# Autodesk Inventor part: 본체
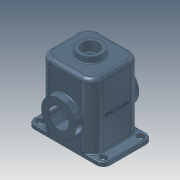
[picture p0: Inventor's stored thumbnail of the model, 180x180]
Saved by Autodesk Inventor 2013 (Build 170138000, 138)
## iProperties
Company: 한국ATC센터
Created: 2014-10
Part Number: 본체
Document SubType Name: Modeling
Designer: 한국ATC센터
Density: 1 g/cm^3
Material: 강철, 연강
Mass: 1088.52 g
Surface Area: 2150.09 cm^2
Volume: 1088.52 cm^3
Author: KYOUNG IL JANG
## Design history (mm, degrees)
sketch "스케치1"
  geometry: L1 (-70, 65)-(70, 65); L2 (70, 65)-(70, -65); L3 (70, -65)-(-70, -65); L4 (-70, -65)-(-70, 65); 3 further points
  constraints: 8 end point, 2 midpoint, 2 parallel, 1 horizontal, 1 horizontal alignment, 1 perpendicular, 1 vertical alignment
  dimensions: "d0" = 140 distance of L2.end L3.end; "d68" = 130 distance of L3.end L1.start
extrude "돌출1" new body sketch "스케치1" distance "d1" = 180; taper "d2" = 0 deg
fillet "모깎기1" dims "d3" = 20
feature "쉘1" dims "d4" = 10
sketch "스케치2"
  geometry: L1 (-70, 45)-(-70, -45) reference; L2 (-50, -65)-(-82, -65); L3 (-82, 65)-(-50, 65); L4 (-85, 57)-(-82, 57); L5 (-82, 41)-(-85, 41); L6 (-100, 47)-(-100, -47); A1 r 20 centre (-50, 45) between (-50, 65) and (-70, 45) reference; A2 r 20 centre (-50, -45) between (-70, -45) and (-50, -65) reference; A3 r 8 centre (-82, 49) between (-82, 41) and (-82, 57); A4 r 8 centre (-85, 49) between (-85, 57) and (-85, 41); A5 r 18 centre (-82, 47) between (-82, 65) and (-100, 47); A6 r 18 centre (-82, -47) between (-100, -47) and (-82, -65); 1 further point
  constraints: 10 end point, 9 tangent, 8 point on circle, 4 centre point, 2 parallel, 2 perpendicular, 1 equal radius
  dimensions: "d6" = 49 vertical distance of point (0, 0) A3.centre; "d8" = 16 distance between parallel lines of L4 L5; "d64" = 18 radius of A5; "d65" = 12 distance from line of A3.centre L1; "d66" = 30 distance between parallel lines of L6 L1; "d67" = 3 distance of A4.centre A3.centre
extrude "돌출2" join sketch "스케치2" distance "d9" = 10; taper "d10" = 0 deg
extrude "돌출3" cut sketch "스케치2" stored distance "d11" = 10; taper "d12" = 0 deg
sketch "스케치3"
  geometry: L1 (-65, 0)-(-65, 180) reference; L2 (-55, 0)-(-55, 170) reference; L3 (-83, 75)-(-51, 75); L4 (45, 0)-(-45, 0) reference; L5 (-83, 75)-(-83, 120.5); L6 (-83, 120.5)-(-55, 120.5); L7 (-55, 120.5)-(-51, 116.5); L8 (-51, 116.5)-(-51, 75); 2 further points
  constraints: 10 end point, 4 perpendicular, 1 point on line
  dimensions: "d13" = 75 distance between parallel lines of L3 L4; "d14" = 18 distance from line of L1 L3.start; "d15" = 4 distance from line of L3.end L2; "d16" = 91 diameter of L6 L3; "d17" = 135 deg angle of L7 L2
revolve "회전1" sketch "스케치3" stored, may be unused: angle "d18" = 90 deg
sketch "스케치4"
  geometry: C1 r 45.5 at (0, 0) reference; 2 further points
  constraints: 1 vertical alignment
  dimensions: "d19" = 35 distance of C1.centre point (0, 35)
hole "구멍1" sketch "스케치4" at (0, 35) diameter "d20" = 3.459; stored, may be unused: countersink angle "d24" = 90 deg, drill point angle "d26" = 118 deg; dims "d21" = 13, "d22" = 4, "d23" = 2, "d25" = 16
fillet "모깎기2" dims "d30" = 3
hole "구멍2" diameter "d33" = 52; stored, may be unused: countersink angle "d37" = 90 deg, drill point angle "d39" = 118 deg; dims "d31" = 10, "d32" = 10, "d34" = 13, "d35" = 4, "d36" = 2, "d38" = 16
sketch "스케치5"
  geometry: C1 r 31 at (0, 0); 1 further point
  constraints: 1 centre point, 1 coincident
  dimensions: "d40" = 62 diameter of C1
extrude "돌출4" join sketch "스케치5" distance "d41" = 15; taper "d42" = 0 deg
hole "구멍3" diameter "d45" = 43; stored, may be unused: countersink angle "d49" = 90 deg, drill point angle "d51" = 118 deg; dims "d43" = 10, "d44" = 10, "d46" = 13, "d47" = 4, "d48" = 2, "d50" = 16
fillet "모깎기3" dims "d52" = 3
fillet "모깎기4" dims "d53" = 3
chamfer "모따기1" distance "d55" = 1; stored, may be unused: second distance "d56" = 2, angle "d57" = 45 deg
sketch "스케치6"
  geometry: 2 further points
  constraints: 1 vertical alignment, 1 other
  dimensions: "d71" = 90 distance of point (0, 0) point (0, 90)
feature "엠보싱2" sketch "스케치6" dims "d0" = 140, "d68" = 130, "d72" = 1, "d73" = 0
fillet "모깎기6" dims "d74" = 10
sketch "스케치7"
  geometry: C1 r 15 at (0, 0); C2 r 21.5 at (0, 0) reference; C3 r 25 at (0, 0); 1 further point
  constraints: 2 centre point, 2 coincident
  dimensions: "d61" = 30 diameter of C1; "d75" = 50 diameter of C3
extrude "돌출5" join sketch "스케치7" distance "d62" = 10; taper "d63" = 0 deg
feature "면 이동1" dims "d76" = 1
fillet "모깎기7" dims "d77" = 3
node "솔리드1"
mirror "대칭1"
mirror "대칭2"
pattern_circular "원형 패턴1" dims angle "d28" = 360 deg
mirror "대칭3"
